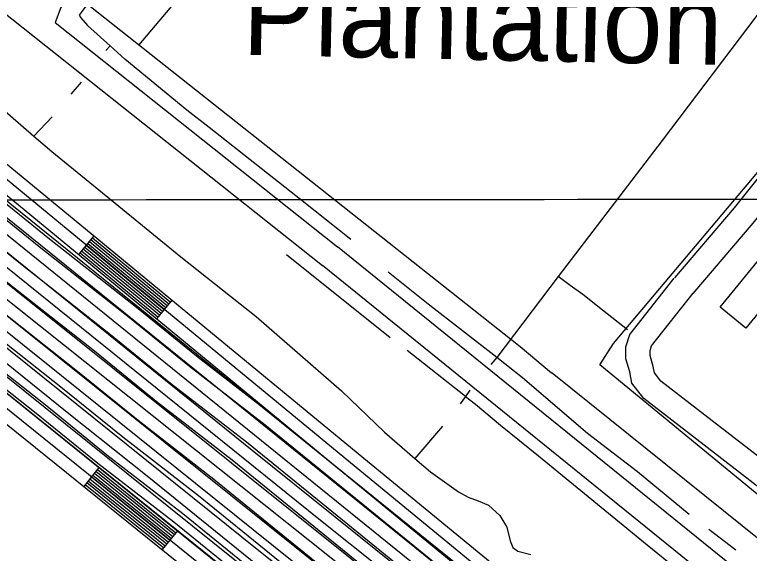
# Model space of a CAD drawing. Extents: x 3297753 to 3335611, y 652252 to 677623.
# Drawn here: x 3308890 to 3309800, y 666289 to 666957 of the extents above; entities that cross this region are included whole.
import ezdxf

# ---------------------------------------------------------------- set-up
doc = ezdxf.new("R2010")
doc.units = 0
for name, color, linetype in [('V-BLDG-IDEN', 7, 'Continuous'), ('V-BLDG-OTLN', 7, 'Continuous'), ('V-GRID-MAJR', 7, 'Continuous'), ('V-RAIL-TRAK', 7, 'Continuous'), ('V-ROAD-CNTR', 7, 'Continuous'), ('V-SITE-OTLN', 7, 'Continuous'), ('V-TOPO-SHOR', 7, 'Continuous'), ('V-UTIL-LINE', 7, 'Continuous')]:
    doc.layers.add(name, color=color, linetype=linetype)

msp = doc.modelspace()

# ---------------------------------------------------------------- linework, layer by layer
at = {"layer": 'V-BLDG-OTLN'}
msp.add_lwpolyline([(3309764.392, 666594.457), (3309818.015, 666659.927), (3309849.89, 666633.819), (3309796.265, 666568.349)], close=True, dxfattribs=at)
at = {"layer": 'V-GRID-MAJR'}
msp.add_spline([(3301864.932, 666722.723), (3307122.83, 666726.164), (3312380.728, 666730.37), (3317638.625, 666735.341), (3322896.522, 666741.077), (3328154.418, 666747.577), (3333412.313, 666754.8420000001), (3333412.3140000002, 666754.8420000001)], degree=3, dxfattribs=at)
at = {"layer": 'V-RAIL-TRAK'}
for points in [[(3308200.234, 667209.25), (3308277.599, 667148.475), (3308385.682, 667060.608), (3308504.503, 666966.625), (3308599.2970000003, 666890.835), (3308713.469, 666797.33), (3308809.3850000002, 666719.647), (3308899.4930000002, 666646.785), (3309006.978, 666562.184), (3309083.5470000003, 666500.036), (3309177.474, 666427.233), (3309272.012, 666350.349), (3309380.648, 666261.943), (3309413.559, 666234.062)], [(3308182.56, 667187.14), (3308259.923, 667126.365), (3308368.006, 667038.498), (3308486.827, 666944.515), (3308581.6210000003, 666868.7270000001), (3308695.795, 666775.219), (3308791.7090000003, 666697.537), (3308881.8170000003, 666624.677), (3308989.302, 666540.074), (3309065.87, 666477.925), (3309159.8000000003, 666405.123), (3309254.336, 666328.2390000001), (3309362.972, 666239.833), (3309395.883, 666211.952)], [(3308159.997, 667163.317), (3308237.362, 667102.545), (3308345.443, 667014.676), (3308464.264, 666920.6950000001), (3308559.058, 666844.905), (3308673.232, 666751.397), (3308769.148, 666673.714), (3308859.256, 666600.855), (3308966.739, 666516.252), (3309043.308, 666454.103), (3309137.237, 666381.303), (3309231.775, 666304.417), (3309340.411, 666216.011), (3309373.322, 666188.129)], [(3308393.221, 667094.314), (3308527.926, 666987.732), (3308622.72, 666911.942), (3308736.894, 666818.434), (3308832.808, 666740.751), (3308922.916, 666667.892), (3309030.401, 666583.291), (3309106.97, 666521.14), (3309200.897, 666448.34), (3309295.435, 666371.454), (3309404.071, 666283.0480000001), (3309436.982, 666255.167)], [(3308440.69, 667076.257), (3308538.674, 666998.816), (3308633.468, 666923.0260000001), (3308708.66, 666861.444), (3308747.642, 666829.52), (3308843.556, 666751.835), (3308933.664, 666678.976), (3309041.149, 666594.375), (3309117.718, 666532.224), (3309211.645, 666459.424), (3309306.183, 666382.54), (3309414.819, 666294.134), (3309447.73, 666266.25)], [(3308249.794, 667018.382), (3308306.791, 666972.044), (3308425.612, 666878.062), (3308520.406, 666802.2710000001), (3308634.58, 666708.7660000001), (3308730.494, 666631.081), (3308820.6040000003, 666558.221), (3308928.0870000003, 666473.621), (3309004.656, 666411.4720000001), (3309098.585, 666338.67), (3309193.123, 666261.786), (3309301.757, 666173.38), (3309334.67, 666145.496)], [(3308393.909, 666940.769), (3308445.199, 666900.201), (3308539.9930000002, 666824.41), (3308654.165, 666730.905), (3308750.0810000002, 666653.2220000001), (3308840.1890000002, 666580.36), (3308947.674, 666495.759), (3309024.2430000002, 666433.611), (3309118.17, 666360.809), (3309212.708, 666283.925), (3309321.344, 666195.519), (3309354.255, 666167.635)], [(3308343.553, 666923.699), (3308414.5840000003, 666867.519), (3308509.378, 666791.728), (3308623.552, 666698.223), (3308719.466, 666620.54), (3308809.573, 666547.678), (3308917.059, 666463.077), (3308993.627, 666400.929), (3309087.557, 666328.127), (3309182.092, 666251.243), (3309290.7290000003, 666162.837), (3309323.642, 666134.953)]]:
    msp.add_lwpolyline(points, dxfattribs=at)
at = {"layer": 'V-ROAD-CNTR'}
for p, q in [((3308988.651985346, 666682.6746078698), (3308969.569023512, 666659.526654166)), ((3309085.102792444, 666603.1627668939), (3309066.01983061, 666580.01481319)), ((3308994.8129730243, 666395.5451821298), (3308975.9800106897, 666372.193228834)), ((3309092.1137784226, 666317.0753390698), (3309073.280816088, 666293.7223857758))]:
    msp.add_line(p, q, dxfattribs=at)
for points in [[(3307508.86794492, 667896.6891798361), (3307549.775863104, 667872.1192289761), (3307590.105782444, 667845.4962822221), (3307642.73267719, 667799.81737358), (3308069.2408241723, 667459.0080551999), (3308529.163904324, 667084.2348047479), (3308567.8888268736, 667044.1258849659), (3308578.374805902, 667032.3139085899), (3308589.8737829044, 667017.0929390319), (3308621.2287201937, 666985.5700020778), (3309315.856330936, 666412.9351473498), (3309592.499777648, 666185.5806020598), (3309626.39370986, 666152.1636688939), (3309672.49361766, 666107.6487579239), (3309700.0395625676, 666081.78580965), (3309750.715461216, 666027.44091834), (3309852.73325718, 665909.2001548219), (3309882.4811976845, 665882.7782076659), (3309935.731091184, 665830.0813130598)], [(3309937.0550885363, 665807.667357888), (3309872.2172182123, 665871.832229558), (3309842.0272785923, 665898.6471759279), (3309739.5474835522, 666017.422938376), (3309689.40858383, 666071.191830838), (3309662.1496383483, 666096.78577965), (3309615.917730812, 666141.427690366), (3309582.451797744, 666174.4226243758), (3309306.3233500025, 666401.354170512), (3308611.1157404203, 666974.467024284), (3308578.519805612, 667007.237958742), (3308566.763829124, 667022.7989276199), (3308556.8798488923, 667033.9329053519), (3308518.994924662, 667073.171826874), (3308059.820843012, 667447.334078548), (3307633.130696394, 667788.2893966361), (3307581.018800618, 667833.5213061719), (3307541.778879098, 667859.425254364), (3307501.8159590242, 667883.4272063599)], [(3307494.7639731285, 667870.165232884), (3307533.781895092, 667846.731279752), (3307571.9318187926, 667821.546330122), (3307623.5287155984, 667776.7614196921), (3308050.4008618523, 667435.6601018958), (3308508.825945, 667062.108849), (3308545.87087091, 667023.7399257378), (3308555.152852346, 667013.28394665), (3308567.16582832, 666997.382978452), (3308601.002760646, 666963.3640464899), (3309296.7903690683, 666389.7731936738), (3309572.4038178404, 666163.2646466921), (3309605.441751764, 666130.691711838), (3309651.805659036, 666085.9228013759), (3309678.777605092, 666060.597852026), (3309728.379505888, 666007.4049584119), (3309831.321300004, 665888.0941970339), (3309861.95323874, 665860.8862514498), (3309916.9301287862, 665806.4793602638)], [(3307468.400025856, 667765.3854424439), (3307532.813897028, 667711.478550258), (3307635.0596925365, 667611.625749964), (3307679.8756029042, 667565.6758418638), (3307867.974226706, 667377.415218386), (3307912.42213781, 667330.3983124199), (3307941.13208039, 667297.3883784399), (3308002.0119586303, 667223.392526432), (3308032.2138982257, 667191.1845908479), (3308075.067812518, 667146.5956800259), (3308104.073754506, 667121.4767302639), (3308140.5536815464, 667088.260796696), (3308386.29119007, 666886.3042006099), (3309252.888456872, 666187.4135983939), (3309336.2262901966, 666123.946725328), (3309361.727239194, 666109.5567541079), (3309491.572979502, 666039.514894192), (3309635.2346921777, 665971.184030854), (3309690.8155810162, 665944.6290839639), (3309735.316492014, 665917.9101374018), (3309907.654147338, 665794.8343835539)], [(3310084.4637937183, 665676.5446201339), (3309917.599127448, 665808.6213559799), (3309869.662223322, 665851.1512709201), (3309840.2712821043, 665882.8632074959), (3309719.434523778, 666015.888941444), (3309673.1816162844, 666064.9428433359), (3309637.877686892, 666099.8047736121), (3309592.1437783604, 666145.477682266), (3309534.6808932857, 666196.034581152), (3309460.68404128, 666257.122458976), (3308014.928932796, 667425.289122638), (3307983.4399957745, 667446.1760808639), (3307953.0660565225, 667466.0020412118), (3307882.0691985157, 667516.7139397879), (3307841.9612787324, 667541.1478909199), (3307607.038748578, 667696.2095807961), (3307572.58281749, 667720.878531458), (3307542.76287713, 667744.455484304), (3307507.92294681, 667770.5094321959)], [(3309910.5191416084, 665774.355424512), (3309727.084508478, 665905.3571625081), (3309683.705595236, 665931.4021104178), (3309628.779705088, 665957.6440579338), (3309484.7869930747, 666026.1329209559), (3309354.480253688, 666096.4227803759), (3309327.9573067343, 666111.3887504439), (3309243.63447538, 666175.6066220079), (3308376.82120901, 666874.6712238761), (3308130.7357011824, 667076.9138193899), (3308094.1127744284, 667110.259752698), (3308064.728833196, 667135.706701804), (3308020.84692096, 667181.365610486), (3307988.4829856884, 667223.1225269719), (3307929.9271028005, 667287.415398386), (3307901.308160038, 667320.319332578), (3307857.2162482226, 667366.960239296), (3307669.200624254, 667555.1378629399), (3307624.448713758, 667601.0217711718), (3307522.745917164, 667700.3445725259)], [(3307512.6779373, 667689.210594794), (3307613.83773498, 667590.4177923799), (3307658.5256456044, 667544.5998840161), (3307846.458269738, 667356.505260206), (3307890.1941822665, 667310.240352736), (3307918.72212521, 667277.4424183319), (3307980.721001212, 667202.1015690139), (3308009.479943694, 667171.5466301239), (3308054.389853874, 667124.817723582), (3308084.1517943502, 667099.042775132), (3308120.917720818, 667065.5668420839), (3308367.3512279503, 666863.0382471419), (3309234.380493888, 666163.799645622), (3309319.688323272, 666098.8307755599), (3309347.233268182, 666083.2888066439), (3309478.001006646, 666012.7509477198), (3309622.324717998, 665944.1040850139), (3309676.5956094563, 665918.1751368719), (3309718.8525249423, 665892.804187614), (3309888.9361847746, 665771.3364305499)], [(3308492.848976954, 667608.195756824), (3308360.01124263, 667442.1710888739), (3308352.72125721, 667418.7191357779), (3308355.878250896, 667394.587184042), (3308367.8062270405, 667369.7942336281), (3308391.4841796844, 667345.6292819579), (3309271.672419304, 666645.831681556)], [(3309869.662223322, 665851.1512709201), (3309686.1185904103, 665997.3509785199), (3309267.16442832, 666331.4373103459), (3307903.255156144, 667432.0841090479), (3307714.0085346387, 667580.450812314)], [(3307703.153556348, 667550.0838730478), (3307768.4784256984, 667480.5640120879), (3307841.716279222, 667405.755161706), (3307881.923198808, 667363.8282455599), (3307935.31709202, 667308.2913566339), (3307973.0120166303, 667265.621441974), (3308026.36690992, 667217.9765372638), (3308078.000806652, 667173.7186257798), (3308131.7646991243, 667125.8217215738), (3308393.009176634, 666918.506136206), (3308955.5580515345, 666464.0740450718), (3309054.695853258, 666385.3622024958), (3309232.4244978, 666240.8954914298), (3309294.426373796, 666192.648587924), (3309337.762287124, 666161.0476511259), (3309364.232234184, 666140.5846920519), (3309401.5741595, 666114.767743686), (3309435.0700925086, 666092.3177885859), (3309465.317032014, 666072.9108273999), (3309510.161942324, 666046.2558807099), (3309729.90850283, 665939.8150935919)], [(3309656.415649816, 666055.8098616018), (3308874.05021455, 666689.23959474), (3307917.2191282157, 667461.029051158)], [(3309683.806595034, 666019.093935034), (3309388.2051862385, 666253.0724670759), (3309184.4365937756, 666416.732139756), (3308594.5307735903, 666893.155186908), (3308178.0406065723, 667232.267508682), (3307879.568203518, 667450.654071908)], [(3308013.3059360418, 667405.52816216), (3308050.1818622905, 667376.754219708), (3309482.712997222, 666218.496536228), (3309540.339881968, 666171.933629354), (3309606.96374872, 666110.336752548), (3309642.4776776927, 666074.493824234), (3309720.3955218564, 665970.0480331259)], [(3307954.389053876, 667287.8263975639), (3307998.3959658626, 667230.0735130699), (3308031.4478997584, 667192.7785876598), (3308076.5578095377, 667143.786685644), (3308097.109768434, 667124.5637240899), (3308130.7867010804, 667090.5857920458), (3308291.91137883, 666961.6520499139), (3309220.2925220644, 666214.57054408), (3309276.2684101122, 666169.0366351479), (3309316.1253303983, 666138.334696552), (3309337.590287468, 666124.4427243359), (3309363.6292353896, 666110.297752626), (3309408.48914567, 666094.021785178)], [(3309187.275588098, 667258.645455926), (3308959.0890444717, 666984.86400349), (3308947.7420671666, 666965.9230413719), (3308940.711081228, 666947.2900786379)], [(3308133.8716949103, 667222.93352735), (3309597.992766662, 666049.6498739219)], [(3309510.161942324, 666046.2558807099), (3309439.378083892, 666078.347816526), (3309408.48914567, 666094.021785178), (3309318.3303259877, 666155.858661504), (3308120.11172243, 667119.320734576), (3308065.889830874, 667166.2576407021), (3308019.060924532, 667211.2855506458)], [(3309901.2051602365, 665808.910355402), (3309695.8455709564, 665965.8450415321), (3309645.9126708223, 665996.7479797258), (3309595.2007722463, 666021.642929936), (3309543.9188748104, 666044.0348851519), (3309509.451943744, 666062.2118487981), (3309480.86900091, 666076.9648192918), (3309461.506039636, 666090.3337925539), (3309428.2391061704, 666110.7807516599), (3309381.290200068, 666144.733683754), (3309347.142268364, 666169.5266341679), (3309192.9965766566, 666292.131388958), (3308063.163836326, 667201.5225701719)], [(3308147.014668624, 667189.385594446), (3309337.493287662, 666239.7024938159), (3309560.9118408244, 666068.4548363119)], [(3309634.040694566, 666002.5759680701), (3309537.5738875, 666059.9068534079), (3309509.451943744, 666076.5038202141), (3309472.571017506, 666098.632775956), (3309452.715057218, 666113.0447471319), (3309427.5741075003, 666130.6687118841), (3309395.601171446, 666152.376668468), (3309353.892254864, 666183.093607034), (3308134.9956926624, 667163.4926462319)], [(3309683.782595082, 665998.1859768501), (3309635.359691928, 666027.15591891), (3309586.9857886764, 666055.417862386), (3309541.6288793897, 666079.1888148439), (3309472.470017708, 666117.6867378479), (3309384.9781926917, 666180.2316127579), (3309337.493287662, 666217.1135389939), (3308203.1375563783, 667127.3437185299)], [(3310105.164752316, 666863.2032468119), (3310072.64281736, 666891.8431895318), (3310052.8718569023, 666911.47915026), (3310035.500891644, 666932.742107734), (3310012.7589371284, 666948.9730752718), (3309985.770991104, 666955.1590628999), (3309961.1820402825, 666946.48908024), (3309930.351101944, 666903.368166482), (3309781.7613991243, 666717.600538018), (3309707.720547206, 666630.592712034)], [(3308940.7100812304, 666947.291078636), (3309290.342381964, 666669.3136345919)], [(3310085.3387919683, 666840.6892918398), (3310052.1408583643, 666869.923233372), (3310030.625901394, 666891.2911906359), (3310014.806933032, 666910.6541519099), (3310000.2109622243, 666921.0711310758), (3309987.544987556, 666923.975125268), (3309980.0820024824, 666921.3431305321), (3309954.2850540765, 666885.262202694), (3309804.90335284, 666698.506576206), (3309730.56850151, 666611.150750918)], [(3308986.7459891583, 666680.357612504), (3309083.196796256, 666600.845771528)], [(3308979.113004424, 666671.098631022), (3309075.563811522, 666591.586790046)], [(3308981.021000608, 666673.4136263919), (3309077.471807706, 666593.901785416)], [(3308982.92999679, 666675.728621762), (3309079.380803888, 666596.216780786)], [(3308984.8379929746, 666678.0426171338), (3309081.288800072, 666598.5307761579)], [(3308971.48001969, 666661.8396495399), (3309067.930826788, 666582.327808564)], [(3308973.388015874, 666664.1546449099), (3309069.8388229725, 666584.6428039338)], [(3308975.2960120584, 666666.4686402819), (3309071.746819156, 666586.956799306)], [(3308977.20500824, 666668.7836356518), (3309073.6558153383, 666589.2717946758)], [(3310091.149780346, 666025.1899228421), (3310028.536905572, 666071.6608299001), (3309290.446381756, 666669.230634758)], [(3310072.4478177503, 666001.7109698), (3310010.1509423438, 666047.946877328), (3309271.568419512, 666645.9146813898)], [(3310155.1716523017, 666105.5607621), (3309669.7226232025, 666481.1330109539), (3309655.0136526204, 666499.9539733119), (3309652.300658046, 666513.9729452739), (3309647.650667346, 666530.4699122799), (3309647.6636673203, 666545.051883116), (3309652.4226578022, 666560.4018524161), (3309707.360547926, 666630.152712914)], [(3310173.97761469, 666128.9427153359), (3309691.04858055, 666502.5649680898), (3309683.095596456, 666512.7399477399), (3309681.516599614, 666520.9049314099), (3309677.654607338, 666534.603904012), (3309677.6596073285, 666540.4958922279), (3309679.430603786, 666546.2078808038), (3309730.92850079, 666611.5907500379)], [(3308989.162984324, 666388.5401961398), (3309086.4627897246, 666310.069353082)], [(3308991.0459805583, 666390.876191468), (3309088.345785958, 666312.4053484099)], [(3308992.9289767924, 666393.2111867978), (3309090.2287821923, 666314.74034374)], [(3308981.628999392, 666379.2002148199), (3309078.9288047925, 666300.729371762)], [(3308983.512995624, 666381.5352101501), (3309080.812801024, 666303.0643670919)], [(3308985.395991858, 666383.8702054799), (3309082.6957972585, 666305.3993624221)], [(3308987.278988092, 666386.20520081), (3309084.578793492, 666307.7343577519)], [(3308977.8630069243, 666374.5292241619), (3309075.1628123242, 666296.058381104)], [(3308979.7460031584, 666376.864219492), (3309077.045808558, 666298.3933764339)]]:
    msp.add_lwpolyline(points, dxfattribs=at)
at = {"layer": 'V-SITE-OTLN'}
msp.add_lwpolyline([(3309632.083, 666549.112), (3310022.901, 667013.656), (3310490.193, 666631.532), (3310561.058, 666572.658), (3310592.433, 666546.591), (3310841.579, 666847.46), (3311019.933, 667063.608), (3311109.058, 666986.808), (3311204.054, 666904.948), (3310748.747, 666321.176), (3311245.403, 665904.899), (3311095.393, 665720.909), (3311086.7, 665723.659), (3311000.026, 665733.86), (3310982.596, 665742.243), (3310853.918, 665858.5), (3310799.849, 665811.527), (3310579.088, 665727.381), (3310415.6380000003, 665854.637), (3310222.775, 666018.93), (3310158.284, 666073.21), (3309942.312, 666253.971), (3309615.185, 666522.898)], close=True, dxfattribs=at)
at = {"layer": 'V-TOPO-SHOR'}
for p, q in [((3308972.832, 666873.482), (3308960.1750000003, 666858.362)), ((3308936.867, 666830.1900000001), (3308914.329, 666806.3690000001)), ((3309355.613, 666556.309), (3309227.12, 666659.262)), ((3309448.799, 666483.523), (3309376.714, 666540.523)), ((3309420.344, 666446.884), (3309386.176, 666406.7980000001)), ((3309783.836, 666292.971), (3309750.472, 666318.653))]:
    msp.add_line(p, q, dxfattribs=at)
for points in [[(3309896.525, 667066.791), (3309830.643, 666983.693), (3309692.35, 666801.116), (3309563.631, 666632.525), (3309487.646, 666531.995), (3309480.2260000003, 666523.106)], [(3308995.452, 666990.511), (3308972.863, 666959.636), (3308970.202, 666956.203), (3308972.289, 666952.844), (3308980.573, 666943.473), (3309008.776, 666918.129), (3309003.435, 666912.62)], [(3309307.049, 666678.095), (3309246.615, 666726.008), (3309131.2430000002, 666817.171), (3309103.781, 666838.457), (3309026.827, 666901.718), (3309008.776, 666918.129)], [(3308868.6520000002, 666845.56), (3308914.329, 666806.3690000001), (3308936.441, 666787.397), (3309010.417, 666727.024), (3309096.074, 666656.835), (3309189.482, 666582.92), (3309295.47, 666490.746), (3309348.548, 666439.278), (3309386.176, 666406.7980000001), (3309405.433, 666390.175), (3309440.417, 666365.339), (3309452.054, 666358.599), (3309464.423, 666354.175), (3309477.576, 666348.996), (3309491.613, 666336.14), (3309500.294, 666321.665), (3309504.398, 666304.812), (3309507.6040000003, 666296.405), (3309513.823, 666291.887), (3309530.037, 666287.523)], [(3309487.646, 666531.995), (3309402.623, 666598.131), (3309353.24, 666637.5650000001)], [(3309649.411, 666566.098), (3309618.619, 666590.7660000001), (3309594.3850000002, 666610.1140000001), (3309578.71, 666621.165), (3309563.631, 666632.525)], [(3309725.7970000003, 666337.24), (3309661.906, 666390.001), (3309600.204, 666437.527), (3309519.4960000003, 666506.892), (3309487.646, 666531.995)], [(3309454.257, 666491.502), (3309448.799, 666483.523), (3309442.309, 666474.358)], [(3309448.799, 666483.523), (3309461.495, 666474.047), (3309492.307, 666448.025), (3309539.259, 666410.057), (3309674.042, 666299.522), (3309782.136, 666211.462), (3309852.4560000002, 666154.888)]]:
    msp.add_lwpolyline(points, dxfattribs=at)
at = {"layer": 'V-UTIL-LINE'}
msp.add_line((3309175.705, 667076.101), (3309044.178, 666919.626), dxfattribs=at)
msp.add_lwpolyline([(3308857.214, 667067.905), (3308974.573, 666974.742), (3308974.573, 666974.742), (3309516.744, 666545.432), (3309516.744, 666545.432), (3309555.433, 666512.737), (3309556.411, 666512.754), (3310050.106, 666115.9890000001), (3310050.106, 666115.9890000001), (3310151.231, 666034.323), (3310151.231, 666034.323), (3310175.948, 666012.442)], dxfattribs=at)

# ---------------------------------------------------------------- texts
at = {"layer": 'V-BLDG-IDEN'}
msp.add_text('Plantation', height=99.99980199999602, rotation=358.78182983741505, dxfattribs=at).set_placement((3309171.9146188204, 666907.2961586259))

doc.saveas('drawing.dxf')
